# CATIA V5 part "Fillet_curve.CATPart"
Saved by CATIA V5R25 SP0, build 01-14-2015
Part number: Part1
Bounding box of the stored display mesh (mm): x -44.747 to 47.153, y -50.22 to 55.347, z 0 to 0
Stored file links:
  E:\cadcim\GSD_cat_v5-6r2014\Part_files\Fillete_curve.CATPart
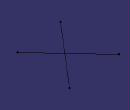
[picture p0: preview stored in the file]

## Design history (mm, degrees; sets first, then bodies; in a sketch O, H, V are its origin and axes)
Body1 (main body)
  Sketch1 on xy-plane, origin (0, 0, 0), H (1, 0, 0), V (0, 1, 0)
    line L1 (-44.7471, 47.4214) -> (39.0352, -41.3682)
    coincidence: L1 O
  Sketch2 on xy-plane, origin (0, 0, 0), H (1, 0, 0), V (0, 1, 0)
    line L1 (47.1532, 55.3475) -> (-42.7846, -50.2197)
    coincidence: L1 O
